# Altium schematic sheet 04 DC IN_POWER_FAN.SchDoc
size 420 x 297 mm
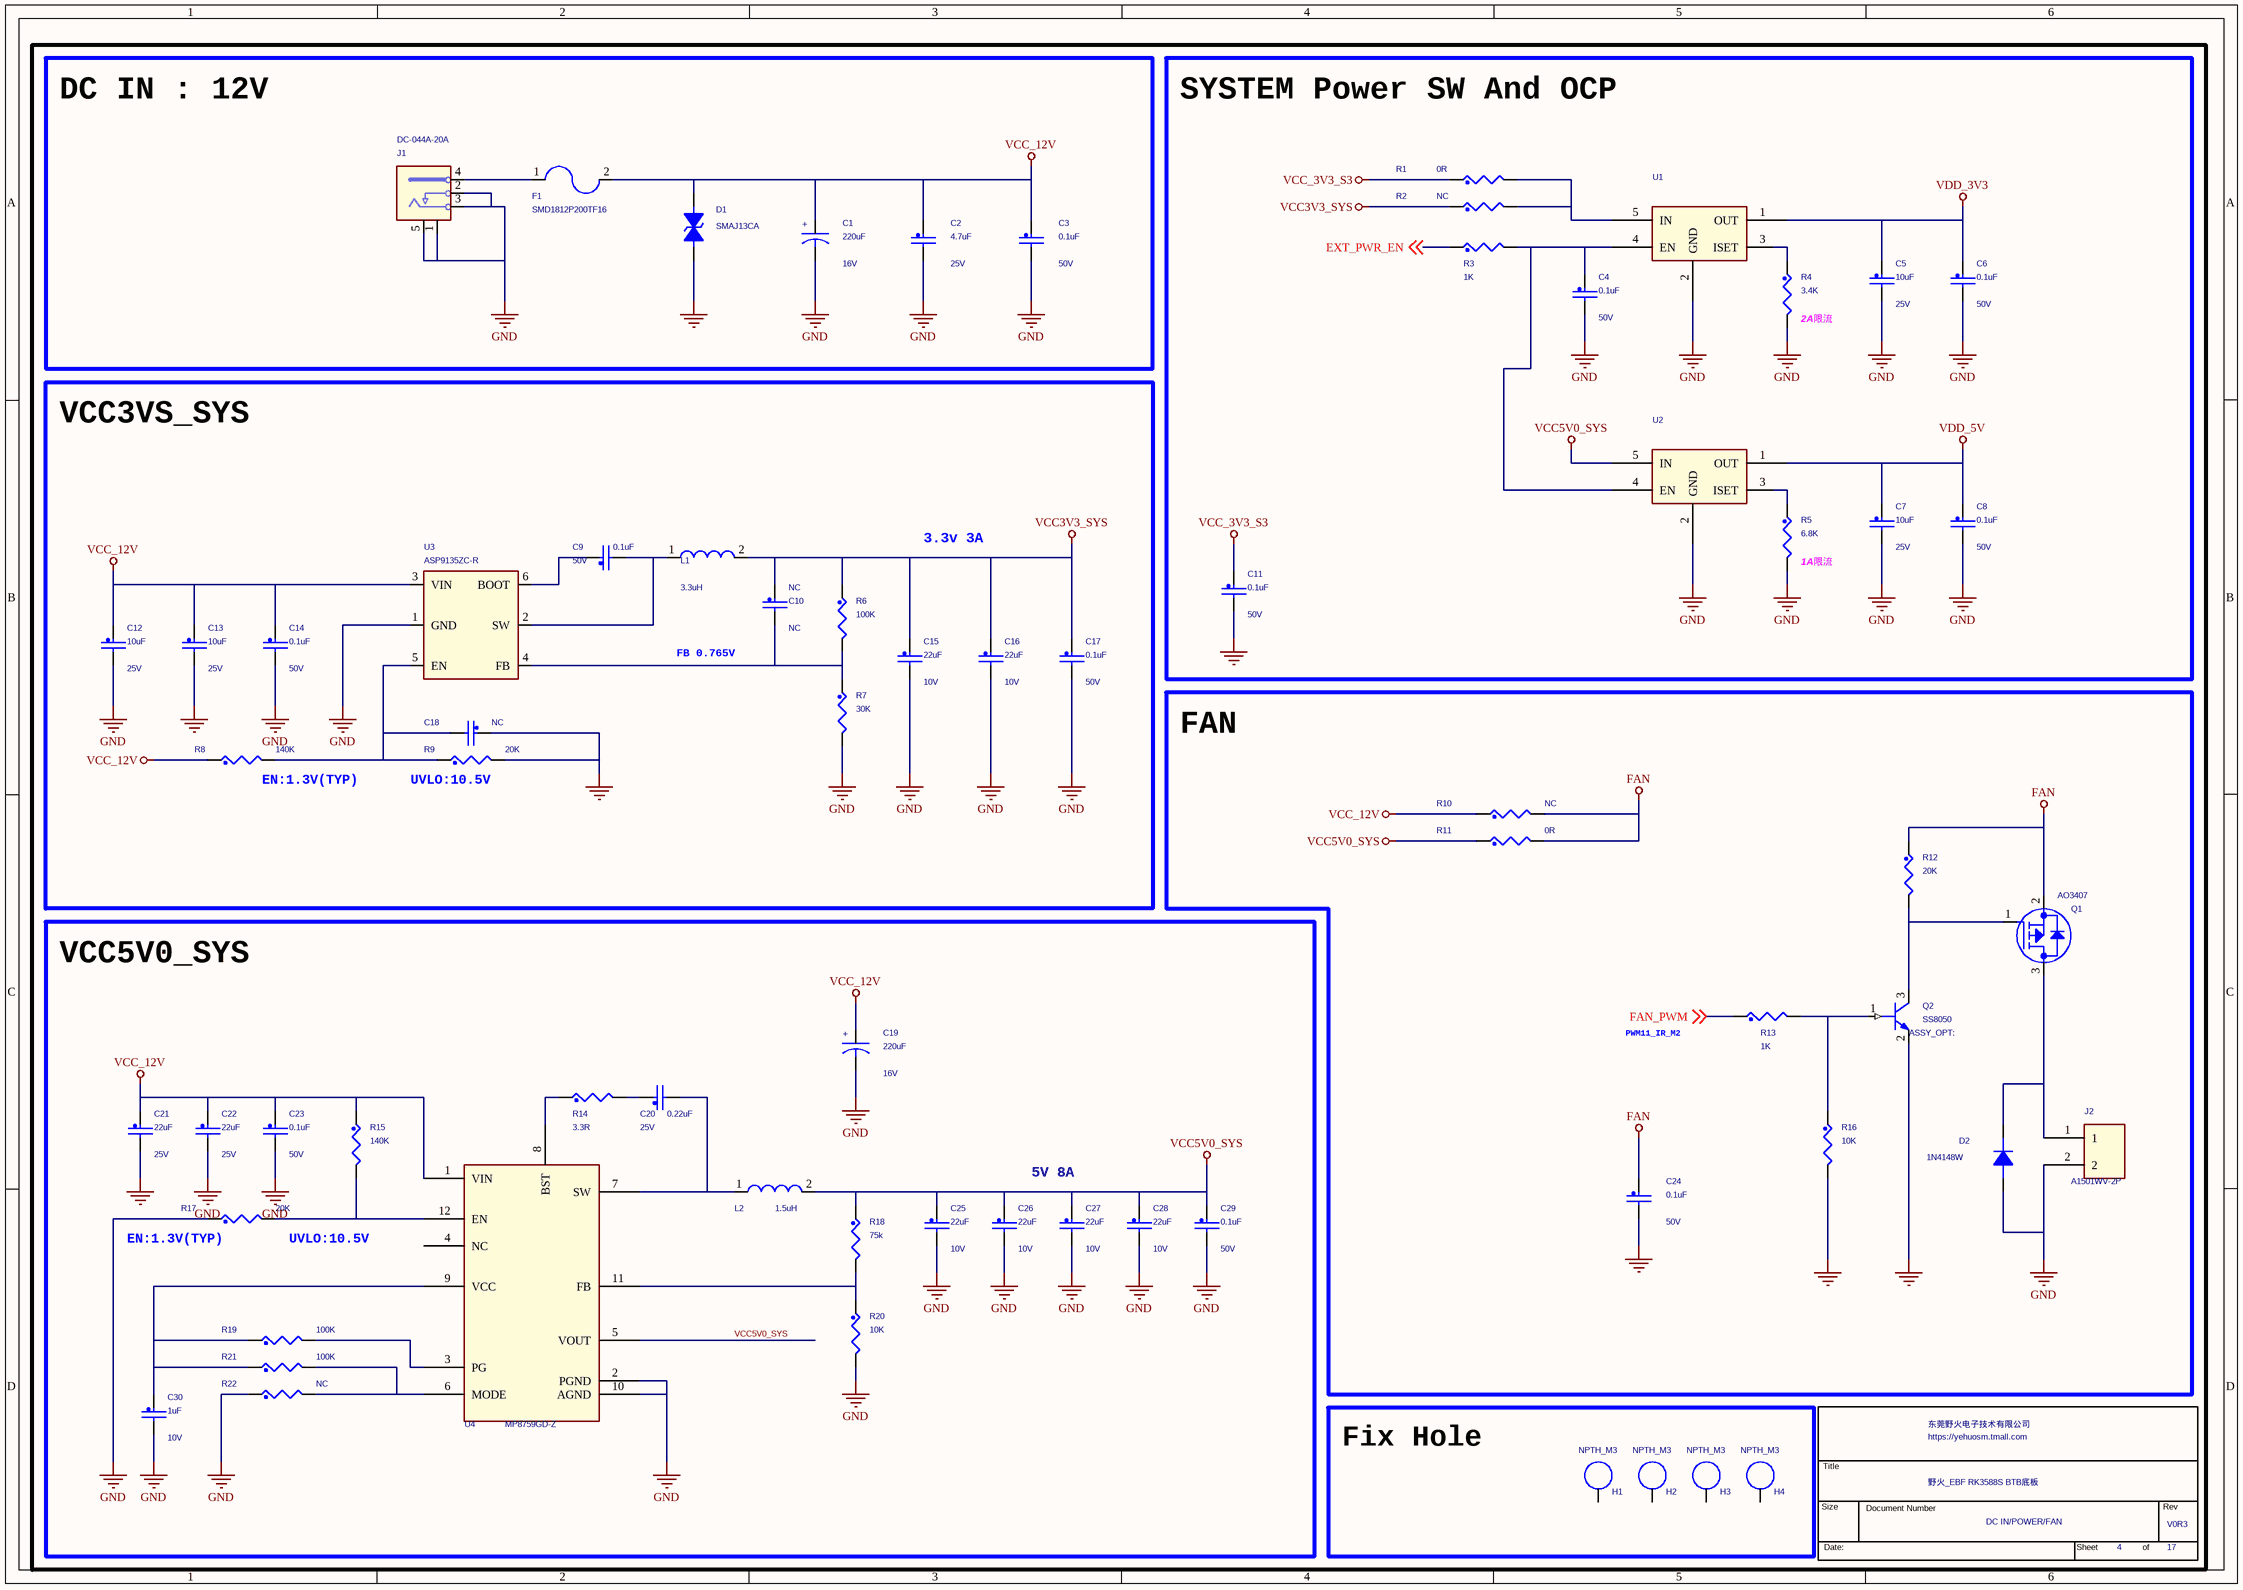
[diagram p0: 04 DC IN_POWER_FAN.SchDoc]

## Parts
*  Page Count: 17  Page Number: 4  OrgName: 东莞野火电子技术有限公司  Title: 野火_EBF RK3588S BTB底板  RevCode: V0R3  Doc: DC IN/POWER/FAN  (hidden comment: TitleBlock_YHSCH)  (graphical)
C1  220uF  Voltage: 16V  [T2012]
C2  4.7uF  Voltage: 25V  [C0603]
C3  0.1uF  Voltage: 50V  [C0402]
C4  0.1uF  Voltage: 50V  [C0402]
C5  10uF  Voltage: 25V  [C0603]
C6  0.1uF  Voltage: 50V  [C0402]
C7  10uF  Voltage: 25V  [C0603]
C8  0.1uF  Voltage: 50V  [C0402]
C9  0.1uF  Voltage: 50V  [C0402]
C10  NC  [C0402]
C11  0.1uF  Voltage: 50V  [C0402]
C12  10uF  Voltage: 25V  [C0603]
C13  10uF  Voltage: 25V  [C0603]
C14  0.1uF  Voltage: 50V  [C0402]
C15  22uF  Voltage: 10V  [C0603]
C16  22uF  Voltage: 10V  [C0603]
C17  0.1uF  Voltage: 50V  [C0402]
C18  NC  [C0402]
C19  220uF  Voltage: 16V  [T2012]
C20  0.22uF  Voltage: 25V  [C0402]
C21  22uF  Voltage: 25V  [C0805]
C22  22uF  Voltage: 25V  [C0805]
C23  0.1uF  Voltage: 50V  [C0402]
C24  0.1uF  Voltage: 50V  [C0402]
C25  22uF  Voltage: 10V  [C0603]
C26  22uF  Voltage: 10V  [C0603]
C27  22uF  Voltage: 10V  [C0603]
C28  22uF  Voltage: 10V  [C0603]
C29  0.1uF  Voltage: 50V  [C0402]
C30  1uF  Voltage: 10V  [C0201]
D1  SMAJ13CA  [D0603/SMD]
D2  1N4148W  [SOD-123]
F1  SMD1812P200TF16  [F1812]
H1  NPTH_M3  [NPTH_M3]
H2  NPTH_M3  [NPTH_M3]
H3  NPTH_M3  [NPTH_M3]
H4  NPTH_M3  [NPTH_M3]
J1  DC-044A-20A  [dc_in_th_3p_10r1x11r6]
J2  A1501WV-2P  [zh1p5mm_th_2p]
L1  3.3uH  [l4520]
L2  1.5uH  [L0518]
Q1  AO3407  [SOT23]
Q2  SS8050  [SOT23]
R1  0R  [R0603]
R2  NC  [R0603]
R3  1K  [R0402]
R4  3.4K  [R0402]
R5  6.8K  [R0402]
R6  100K  [R0402]
R7  30K  [R0402]
R8  140K  [R0402]
R9  20K  [R0402]
R10  NC  [R0603]
R11  0R  [R0603]
R12  20K  [R0402]
R13  1K  [R0402]
R14  3.3R  [R0402]
R15  140K  [R0402]
R16  10K  [R0402]
R17  20K  [R0402]
R18  75k  [R0402]
R19  100K  [R0402]
R20  10K  [R0402]
R21  100K  [R0402]
R22  NC  [R0402]
U1  (no value)  [SOT23-5]
U2  (no value)  [SOT23-5]
U3  ASP9135ZC-R  [SOT23_6]
U4  MP8759GD-Z  [QFN12-2R00X3R00]

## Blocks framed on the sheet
DC IN : 12V: C1-C3 D1 F1 J1
SYSTEM Power SW And OCP: C4-C8 C11 R1-R5 U1 U2
VCC3VS_SYS: C9 C10 C12-C18 L1 R6-R9 U3
FAN: C24 D2 J2 Q1 Q2 R10-R13 R16
VCC5V0_SYS: C19-C23 C25-C30 L2 R14 R15 R17-R22 U4
Fix Hole: H1-H4

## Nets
FAN: C24.1 Q1.2(SOURCE) R10.2 R11.2 R12.1
GND: C1.2 C2.2 C3.2 C4.2 C5.2 C6.2 C7.2 C8.2 C11.2 C12.2 C13.2 C14.2 C15.2 C16.2 C17.2 C18.1 C19.2 C21.2 C22.2 C23.2 C24.2 C25.2 C26.2 C27.2 C28.2 C29.2 C30.2 D1.1 D2.2(A) J1.1 J1.2 J1.3 J1.5 J2.2 Q2.2(EMITTER) R4.2 R5.2 R7.2 R9.2 R16.2 R17.1 R20.2 R22.1 U1.2(GND) U2.2(GND) U3.1(GND) U4.2(PGND) U4.10(AGND)
VCC3V3_SYS: C10.1 C15.1 C16.1 C17.1 L1.2 R2.1 R6.1
VCC5V0_SYS: C25.1 C26.1 C27.1 C28.1 C29.1 L2.2 R11.1 R18.1 U2.5(IN) U4.5(VOUT)
VCC_3V3_S3: C11.1 R1.1
VCC_12V: C1.1 C2.1 C3.1 C12.1 C13.1 C14.1 C19.1 C21.1 C22.1 C23.1 D1.2 F1.2 R8.1 R10.1 R15.1 U3.3(VIN) U4.1(VIN)
VDD_3V3: C5.1 C6.1 U1.1(OUT)
VDD_5V: C7.1 C8.1 U2.1(OUT)
EXT_PWR_EN: R3.1 ; off-sheet EXT_PWR_EN
FAN_PWM: R13.1 ; off-sheet FAN_PWM
NetC4_1: C4.1 R3.2 U1.4(EN) U2.4(EN)
NetC9_1: C9.1 U3.6(BOOT)
NetC9_2: C9.2 L1.1 U3.2(SW)
NetC10_2: C10.2 R6.2 R7.1 U3.4(FB)
NetC18_2: C18.2 R8.2 R9.1 U3.5(EN)
NetC20_1: C20.1 R14.2
NetC20_2: C20.2 L2.1 U4.7(SW)
NetC30_1: C30.1 R19.1 R21.1 U4.9(VCC)
NetD2_1: D2.1(K) J2.1 Q1.3(DRAIN)
NetF1_1: F1.1 J1.4
NetQ1_1: Q1.1(GATE) Q2.3(COLLECTOR) R12.2
NetQ2_1: Q2.1(BASE) R13.2 R16.1
NetR1_2: R1.2 R2.2 U1.5(IN)
NetR4_1: R4.1 U1.3(ISET)
NetR5_1: R5.1 U2.3(ISET)
NetR14_1: R14.1 U4.8(BST)
NetR15_2: R15.2 R17.2 U4.12(EN)
NetR18_2: R18.2 R20.1 U4.11(FB)
NetR19_2: R19.2 U4.3(PG)
NetR21_2: R21.2 R22.2 U4.6(MODE)

Not connected (* = marked no-connect by the designer): H1 1(NC_1); H2 1(NC_1); H3 1(NC_1); H4 1(NC_1); U4 4(NC)

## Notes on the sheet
- (near R4) 2A限流
- 3.3v 3A
- (near R5) 1A限流
- FB 0.765V
- (near R8) EN:1.3V(TYP)
- (near R9) UVLO:10.5V
- PWM11_IR_M2
- 5V 8A
- (near R17) EN:1.3V(TYP)
- (near R17) UVLO:10.5V

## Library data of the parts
* = TitleBlock_YHSCH: Cage Code: 1
C1 = CAP: 生命周期: 量产; 价格: 0.566564; 规格书: 台湾立隆-贴片型铝电解电容.pdf; 类别: 贴片型铝电解电容; 品牌: 台湾立隆; 条码: EBF29060148; 规格编号: VZT221M1CTR-0606ACS; 规格: 贴片电解电容220uF 20% 16V 尺寸6.3mmX5.8mm 工作寿命：2000H@105℃
C2 = CAP_NP: CLASS: DISCRETE; 规格: 贴片电容4.7uF 10% 25V X7R 0603; 规格编号: CL10A475KA8NQNC; 条码: EBF29060162; 品牌: 三星; 类别: 贴片电容0603; 规格书: 三星电容.pdf; 价格: 0.031274; 生命周期: 量产
C3 C4 C9 C17 C24 = CAP_NP: CLASS: DISCRETE; 规格: 贴片电容0.1uF 10% 50V X5R 0402; 规格编号: 0402X104K500NT; 条码: EBF29060118; 品牌: 风华; 类别: 贴片电容0402; 规格书: 风华电容.pdf; 价格: 0.029826; 生命周期: 量产
C5 = CAP_NP: CLASS: DISCRETE; 规格: 贴片电容10uF 20% 25V X5R 0603; 规格编号: CL10A106MA8NRNC; 条码: EBF29060171; 品牌: 三星; 类别: 贴片电容0603; 规格书: 三星电容.pdf; 价格: 0.109811; 生命周期: 量产
C6 C8 C14 C23 = CAP_NP: CLASS: DISCRETE; 生命周期: 量产; 价格: 0.029826; 规格书: 风华电容.pdf; 类别: 贴片电容0402; 品牌: 风华; 条码: EBF29060118; 规格编号: 0402X104K500NT; 规格: 贴片电容0.1uF 10% 50V X5R 0402
C7 = CAP_NP: CLASS: DISCRETE; 生命周期: 量产; 价格: 0.109811; 规格书: 三星电容.pdf; 类别: 贴片电容0603; 品牌: 三星; 条码: EBF29060171; 规格编号: CL10A106MA8NRNC; 规格: 贴片电容10uF 20% 25V X5R 0603
C10 C18 = CAP_NP: CLASS: DISCRETE; 类别: 贴片电容0402; 条码: EBF29060149; 规格: 贴片电容NC 预留
C11 = CAP_NP_Dup1: CLASS: DISCRETE; 生命周期: 量产; 价格: 0.029826; 规格书: 风华电容.pdf; 类别: 贴片电容0402; 品牌: 风华; 条码: EBF29060118; 规格编号: 0402X104K500NT; 规格: 贴片电容0.1uF 10% 50V X5R 0402
C12 C13 = CAP_NP: CLASS: DISCRETE; 规格: 贴片电容10uF 20% 25V X5R 0603; 规格编号: CL10A106MA8NRNC; 条码: EBF29060171; 品牌: 三星; 类别: 贴片电容0603; 规格书: 三星电容.pdf; 生命周期: 量产; 价格: 0.109811
C15 = CAP_NP: CLASS: DISCRETE; 生命周期: 量产; 价格: 0.078818; 规格书: 三星电容.pdf; 类别: 贴片电容0603; 品牌: 三星; 条码: EBF29060163; 规格编号: CL10A226MP8NUNE; 规格: 贴片电容22uF 20% 10V X5R 0603
C16 C25-C28 = CAP_NP: CLASS: DISCRETE; 规格: 贴片电容22uF 20% 10V X5R 0603; 规格编号: CL10A226MP8NUNE; 条码: EBF29060163; 品牌: 三星; 类别: 贴片电容0603; 规格书: 三星电容.pdf; 价格: 0.078818; 生命周期: 量产
C19 = CAP: 规格: 贴片电解电容220uF 20% 16V 尺寸6.3mmX5.8mm 工作寿命：2000H@105℃; 规格编号: VZT221M1CTR-0606ACS; 条码: EBF29060148; 品牌: 台湾立隆; 类别: 贴片型铝电解电容; 规格书: 台湾立隆-贴片型铝电解电容.pdf; 价格: 0.566564; 生命周期: 量产
C20 = CAP_NP: CLASS: DISCRETE; 备注: 新增0402物料; 规格: 贴片电容0.22uF 20% 25V X7R 0402; 规格编号: TCC0402X7R224K250AT; 条码: EBFCIS241220094109; 品牌: CCTC; 类别: 贴片电容0402; 规格书: CCTC_TCC0402X5R105K6R3AT; 价格: 0.0073; 生命周期: 量产
C21 = CAP_NP: CLASS: DISCRETE; 生命周期: 量产; 价格: 0.285631; 规格书: 风华电容.pdf; 类别: 贴片电容0805; 品牌: 风华; 条码: EBF29060173; 规格编号: 0805X226M250NT; 规格: 贴片电容22uF 20% 25V X5R 0805
C22 = CAP_NP: CLASS: DISCRETE; 规格: 贴片电容22uF 20% 25V X5R 0805; 规格编号: 0805X226M250NT; 条码: EBF29060173; 品牌: 风华; 类别: 贴片电容0805; 规格书: 风华电容.pdf; 价格: 0.285631; 生命周期: 量产
C29 = CAP_NP: CLASS: DISCRETE; 价格: 0.029826; 生命周期: 量产; 规格书: 风华电容.pdf; 类别: 贴片电容0402; 品牌: 风华; 条码: EBF29060118; 规格编号: 0402X104K500NT; 规格: 贴片电容0.1uF 10% 50V X5R 0402
C30 = CAP_NP: CLASS: DISCRETE; 生命周期: 量产; 价格: 0.036418; 规格书: 村田0201系列贴片电容.pdf; 类别: 贴片电容0201; 品牌: 村田; 条码: EBF29060299; 规格编号: GRM033R61A105M; 规格: 贴片电容1uF 20% 10V X5R 0201
D1 = DIODE BI-DIR TRIG: 规格: TVS二极管 箝位电压21.5V 击穿电压14.4V 反向关断电压13V; 条码: EBF29140049; 品牌: 伯恩半导体; 类别: 贴片TVS; 规格书: 伯恩半导体-SMAJ13CA.pdf; 价格: 0.181964; 生命周期: 量产
D2 = DIODE: 规格: 开关二极管 反向耐压值100V 平均整流电流150mA 正向压降1.25V 150mA 功率500mW; 条码: EBF29140015; 品牌: 江苏长电; 类别: 贴片开关二极管; 规格书: 1N4148WT4.pdf; 价格: 0.061637; 生命周期: 量产; 丝印: T4
F1 = FUSE: 生命周期: 量产; 价格: 0.385618; 规格书: 瑞隆源-自恢复保险丝.pdf; 类别: 自恢复保险丝; 品牌: 瑞隆源; 条码: EBF29270006; 规格: 自恢复保险丝 最大电压46V 最大电流100A 保持电流2A 跳闸电流4A
H1 H4 = SPACER: CLASS: IC; 生命周期: 量产; 类别: M3螺丝孔; 品牌: 野火; 条码: EBFCIS220926102704; 规格编号: M3螺丝孔_无铜
H2 H3 = SPACER: CLASS: IC; 规格编号: M3螺丝孔_无铜; 条码: EBFCIS220926102704; 品牌: 野火; 类别: M3螺丝孔; 生命周期: 量产
J1 = DC-044A-20A: 规格: DC-044A-20A DC插座; 规格编号: DC-044A-20A DC; 条码: EBF29040093; 类别: DC电源座; 规格书: DC插座_内径_2MM外径_5.9MM.pdf; 生命周期: 量产
J2 = 1X2PIN: 生命周期: 量产; 规格书: 长江连接器_A1501WV-2P.PDF; 类别: 线对板连接器; 品牌: 长江连接器; 条码: EBF29040095; 规格: ZH1.5直插 镀锡 2P 针座连接器
L1 = IND: CLASS: DISCRETE; 规格: 贴片电感3.3uH ±20% 3A 直流电阻69mΩ; 条码: EBF29050040; 品牌: 台庆; 类别: 贴片电感0402; 规格书: 台庆-功率电感.pdf; 生命周期: 量产; 规格编号: TMPC0402HP-3R3MG-Z02; 价格: 1.5992
L2 = IND: CLASS: DISCRETE; 规格: 贴片电感1.5uH ±20% 7.5A 直流电阻25mΩ; 规格编号: FXL0518-1R5-M; 条码: EBFCIS221116170516; 品牌: 长江微电; 类别: 贴片电感SMD; 规格书: 长江微电_FXL0518-1R5-M.pdf; 价格: 0.525895; 生命周期: 量产
Q1 = MOSFET_P: CLASS: IC; 规格: P沟道MOS 导通电阻60mΩ 电流4.1A 3V可驱动; 条码: EBF29280012; 品牌: 合科泰; 类别: P-MOS; 规格书: 合科泰-AO3407.pdf; 价格: 0.199827; 生命周期: 量产; 丝印: A7
Q2 = NPN: CLASS: IC; 丝印: Y1; 生命周期: 量产; 价格: 0.086744; 规格书: 江苏长电-SS8050Y1.pdf; 类别: 贴片三极管SOT-23; 品牌: 江苏长电; 条码: EBF29090001; 规格: 贴片三极管SS8050 集电极电流1.5A 额定功率300mW NPN
R1 = RES: CLASS: DISCRETE; 规格: 贴片电阻0R 1% 1/10W 0603; 条码: EBF29070063; 类别: 贴片电阻0603; 规格编号: RI0603L0000FT; 品牌: 合科泰; 规格书: 合科泰-RI系列电阻.pdf; 生命周期: 量产
R2 R10 = RES: CLASS: DISCRETE; 规格: 贴片电阻NC 预留; 条码: EBF29070088; 类别: 贴片电阻0603
R3 = RES: CLASS: DISCRETE; 生命周期: 量产; 规格书: 合科泰-RI系列电阻.pdf; 类别: 贴片电阻0402; 品牌: 合科泰; 条码: EBF29070050; 规格编号: RI0402L1001FT; 规格: 贴片电阻1K 1% 1/16W 0402
R4 = RES: CLASS: DISCRETE; 生命周期: 量产; 规格书: 合科泰-RI系列电阻.pdf; 类别: 贴片电阻0402; 品牌: 合科泰; 条码: EBF29070186; 规格编号: RI0402L3401FT; 规格: 贴片电阻3.4K 1% 1/16W 0402
R5 = RES: CLASS: DISCRETE; 规格: 贴片电阻6.8K 1% 1/16W 0402; 规格编号: RI0402L6801FT; 条码: EBF29070052; 品牌: 合科泰; 类别: 贴片电阻0402; 规格书: 合科泰-RI系列电阻.pdf; 生命周期: 量产
R6 = RES: CLASS: DISCRETE; 生命周期: 量产; 规格书: 合科泰-RI系列电阻.pdf; 类别: 贴片电阻0402; 品牌: 合科泰; 条码: EBF29070054; 规格编号: RI0402L1003FT; 规格: 贴片电阻100K 1% 1/16W 0402
R7 = RES: CLASS: DISCRETE; 规格: 贴片电阻30K 1% 1/16W 0402; 规格编号: RI0402L3002FT; 条码: EBF29070048; 品牌: 合科泰; 类别: 贴片电阻0402; 规格书: 合科泰-RI系列电阻.pdf; 生命周期: 量产
R8 = RES: CLASS: DISCRETE; 生命周期: 量产; 规格书: 合科泰-RI系列电阻.pdf; 品牌: 合科泰; 规格编号: RI0402L1403FT; 规格: 贴片电阻140K 1% 1/16W 0402; 条码: EBF29070058; 类别: 贴片电阻0402
R9 = RES: CLASS: DISCRETE; 生命周期: 量产; 价格: 0.002473; 规格书: 厚声-无铅厚膜电阻.pdf; 品牌: 厚声; 规格编号: 0402WGF2002TCE; 类别: 贴片电阻0402; 条码: EBF29070223; 规格: 贴片电阻20K 1% 1/16W 0402
R11 = RES: CLASS: DISCRETE; 生命周期: 量产; 规格书: 合科泰-RI系列电阻.pdf; 类别: 贴片电阻0603; 品牌: 合科泰; 条码: EBF29070063; 规格编号: RI0603L0000FT; 规格: 贴片电阻0R 1% 1/10W 0603
R12 = RES: CLASS: DISCRETE; 生命周期: 量产; 价格: 0.002473; 规格书: 厚声-无铅厚膜电阻.pdf; 类别: 贴片电阻0402; 品牌: 厚声; 条码: EBF29070223; 规格编号: 0402WGF2002TCE; 规格: 贴片电阻20K 1% 1/16W 0402
R13 = RES: CLASS: DISCRETE; 规格: 贴片电阻1K 1% 1/16W 0402; 规格编号: RI0402L1001FT; 条码: EBF29070050; 品牌: 合科泰; 类别: 贴片电阻0402; 规格书: 合科泰-RI系列电阻.pdf; 生命周期: 量产
R14 = RES: CLASS: DISCRETE; 价格: 0.003117; 规格: 贴片电阻3.3R 1% 1/16W 0402; 规格编号: 0402WGF330KTCE; 条码: EBFCIS221116113428; 品牌: 厚声; 类别: 贴片电阻0402; 规格书: 厚声-无铅厚膜电阻.pdf; 生命周期: 量产
R15 = RES: CLASS: DISCRETE; 生命周期: 量产; 规格书: 合科泰-RI系列电阻.pdf; 类别: 贴片电阻0402; 品牌: 合科泰; 条码: EBF29070058; 规格编号: RI0402L1403FT; 规格: 贴片电阻140K 1% 1/16W 0402
R16 = RES: CLASS: DISCRETE; 生命周期: 量产; 价格: 0.002773; 规格书: 厚声-无铅厚膜电阻.pdf; 类别: 贴片电阻0402; 品牌: 厚声; 条码: EBF29070046; 规格编号: 0402WGF1002TCE; 规格: 贴片电阻10K 1% 1/16W 0402
R17 = RES: CLASS: DISCRETE; 规格: 贴片电阻20K 1% 1/16W 0402; 条码: EBF29070223; 类别: 贴片电阻0402; 规格编号: 0402WGF2002TCE; 品牌: 厚声; 规格书: 厚声-无铅厚膜电阻.pdf; 价格: 0.002473; 生命周期: 量产
R18 = RES: CLASS: DISCRETE; 生命周期: 量产; 价格: 0.002211; 规格书: 国巨贴片电阻.pdf; 类别: 贴片电阻0402; 品牌: 国巨; 条码: EBFCIS221202111303; 规格编号: RC0402FR-0775KL; 规格: 贴片电阻75K 1% 1/16W 0402
R19 = RES: CLASS: DISCRETE; 规格: 贴片电阻100K 1% 1/16W 0402; 规格编号: RI0402L1003FT; 条码: EBF29070054; 品牌: 合科泰; 类别: 贴片电阻0402; 规格书: 合科泰-RI系列电阻.pdf; 生命周期: 量产
R20 = RES: CLASS: DISCRETE; 规格: 贴片电阻10K 1% 1/16W 0402; 规格编号: 0402WGF1002TCE; 条码: EBF29070046; 品牌: 厚声; 类别: 贴片电阻0402; 规格书: 厚声-无铅厚膜电阻.pdf; 价格: 0.002773; 生命周期: 量产
R21 = RES: CLASS: DISCRETE; 规格: 贴片电阻100K 1% 1/16W 0402; 条码: EBF29070054; 类别: 贴片电阻0402; 规格编号: RI0402L1003FT; 品牌: 合科泰; 规格书: 合科泰-RI系列电阻.pdf; 生命周期: 量产
R22 = RES: CLASS: DISCRETE; 规格: 贴片电阻NC 预留; 条码: EBF29070087; 类别: 贴片电阻0402
U1 U2 = LPW5209AB5F: 规格: 集成电源开关 导通电阻：80mΩ 最大可设置保护电流：2.1A 输入电压：2.5V~6V 静态电流：30uA 其他功能：软启动、短路保护、热保护; 条码: EBF29280015; 品牌: 微源半导体; 类别: 功率开关; 规格书: 微源半导体_LPW5209AB5F.pdf; 价格: 0.468063; 生命周期: 量产
U3 = TP6327GS6: 生命周期: 量产; 规格书: 安森德_ASP9135ZC-R.pdf; 类别: 电源管理-DCDC; 品牌: 安森德; 条码: EBFCIS240710113940; 规格: DC-DC电源芯片 可输出电流 3A 开关工作频率 600kHz 输出类型 ADJ 输入电压范围：4V-18V; 备注: RK3566金手指与BTB底板替换物料
U4 = MP8759GD-Z: 规格: DC-DC电源芯片 输入：4.5V-26V 电流：8A 频率: 固定700KHz频率  FB：0.6V; 条码: EBFCIS221112174800; 品牌: MPS; 类别: 电源管理-DCDC; 规格书: MPS_MP8759GD-Z.pdf; 价格: 3.2; 生命周期: 量产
